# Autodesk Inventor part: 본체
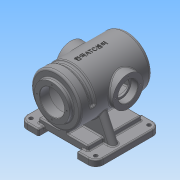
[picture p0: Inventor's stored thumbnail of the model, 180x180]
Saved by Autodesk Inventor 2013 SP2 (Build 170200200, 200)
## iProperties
Created: 2015-10
Part Number: 본체
Document SubType Name: Modeling
Designer: mdu
Density: 2.71 g/cm^3
Material: 알루미늄 6061
Mass: 4592.12 g
Surface Area: 2715.66 cm^2
Volume: 1694.51 cm^3
Author: mdu
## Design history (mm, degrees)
sketch "스케치1"
  geometry: L1 (-100, 85)-(-50, 85); L2 (-50, 85)-(-50, -85); L3 (-50, -85)-(-100, -85); L4 (-100, -85)-(-100, 85); L5 (50, 85)-(100, 85); L6 (100, 85)-(100, -85); L7 (100, -85)-(50, -85); L8 (50, -85)-(50, 85); 3 further points
  constraints: 16 end point, 4 parallel, 2 equal length, 2 horizontal, 2 horizontal alignment, 2 midpoint, 2 perpendicular
  dimensions: "d0" = 100 distance between parallel lines of L8 L2; "d1" = 170 distance of L3.end L1.start; "d3" = 200 distance between parallel lines of L6 L4; "d4" = 50 distance from line of point (0, 0) L2 (= 0.5 x d0)
extrude "돌출1" new body sketch "스케치1" distance "d5" = 16; taper "d6" = 0 deg
node "작업 평면1"
sketch "스케치2"
  geometry: L1 (-65, 70)-(65, 70); L2 (65, 70)-(65, -70); L3 (65, -70)-(-65, -70); L4 (-65, -70)-(-65, 70); 3 further points
  constraints: 8 end point, 2 midpoint, 2 parallel, 1 horizontal, 1 horizontal alignment, 1 perpendicular, 1 vertical alignment
  dimensions: "d8" = 130 distance of L2.end L3.end; "d9" = 140 distance of L1.end L2.end
extrude "돌출2" join sketch "스케치2" distance "d10" = 20; taper "d11" = 0 deg
sketch "스케치3"
  geometry: L1 (-100, 110)-(100, 110); L2 (85, 0)-(-85, 0) reference; L3 (100, 110)-(100, 175); L4 (100, 175)-(-90, 175); L5 (-90, 175)-(-90, 156); L6 (-90, 156)-(-100, 156); L7 (-100, 156)-(-100, 110); L8 (90, 110)-(90, 165); L9 (90, 165)-(-75, 165); L10 (-75, 165)-(-75, 110); L11 (-100, 142.5)-(-75, 142.5); 3 further points
  constraints: 20 end point, 5 perpendicular, 4 parallel, 4 point on line, 2 midpoint, 1 horizontal, 1 vertical alignment
  dimensions: "d12" = 110 distance from line of L2 L1.end; "d13" = 200 distance of L1.start L1.end; "d14" = 130 diameter of L4 L1; "d15" = 92 diameter of L6 L1; "d16" = 10 distance of L5.end L6.end; "d42" = 110 diameter of L9 L1; "d43" = 10 distance between parallel lines of L3 L8; "d44" = 25 distance between parallel lines of L10 L7; "d45" = 65 diameter of L11 L1
revolve "회전1" sketch "스케치3" stored, may be unused: angle "d17" = 90 deg
sketch "스케치4"
  geometry: L1 (-50, 70)-(50, 70) reference; L2 (50, -70)-(-50, -70) reference; L3 (-10, 70)-(-10, -70); L4 (10, -70)-(10, 70); 1 further point
  constraints: 4 end point, 4 point on line, 2 perpendicular
  dimensions: "d18" = 20 distance between parallel lines of L4 L3; "d19" = 10 distance from line of point (0, 0) L3
extrude "돌출3" join sketch "스케치4" stored distance "d20" = 10; taper "d21" = 0 deg
node "작업 평면2"
sketch "스케치5"
  geometry: L1 (-50, -8)-(0, -8) reference; L2 (100, -8)-(150, -8) reference; L3 (-40, -8)-(-8.943, -74.601); L4 (140, -8)-(108.943, -74.601); L5 (-50, 8)-(-50, -8) reference; L6 (150, 8)-(150, -8) reference; A1 r 65 centre (50, -102) between (-8.943, -74.601) and (108.943, -74.601) reference; 1 further point
  constraints: 4 end point, 2 point on circle, 2 point on line, 1 equal length
  dimensions: "d23" = 10 distance from line of L3.start L5; "d24" = 10 distance from line of L4.start L6; "d25" = 25 deg angle of L3 L5
feature "리브1" sketch "스케치5" dims "d26" = 1, "d27" = 20, "d28" = 0
node "작업 평면3"
sketch "스케치6"
  geometry: L1 (100, 156)-(100, 64) reference; C1 r 40 at (-25, 110); 2 further points
  constraints: 1 centre point, 1 horizontal alignment, 1 midpoint
  dimensions: "d37" = 80 diameter of C1; "d38" = 125 distance from line of C1.centre L1
extrude "돌출4" join sketch "스케치6" stored distance "d39" = 10; taper "d40" = 0 deg
hole "구멍1" diameter "d48" = 42; stored, may be unused: countersink angle "d52" = 90 deg, drill point angle "d54" = 118 deg; dims "d46" = 10, "d47" = 10, "d49" = 6, "d50" = 52, "d51" = 18, "d53" = 8
sketch "스케치7"
  geometry: C1 r 40 at (0, 0) reference; 2 further points
  constraints: 1 horizontal alignment
  dimensions: "d55" = 32.5 distance of point (32.5, 0) C1.centre
hole "구멍2" sketch "스케치7" at (32.5, 0) diameter "d56" = 3.242; stored, may be unused: countersink angle "d60" = 90 deg, drill point angle "d62" = 118 deg; dims "d57" = 11, "d58" = 52, "d59" = 18, "d61" = 13
sketch "스케치8"
  geometry: C1 r 46 at (0, 0) reference; 2 further points
  constraints: 1 vertical alignment
  dimensions: "d66" = 39 distance of C1.centre point (0, 39)
hole "구멍3" sketch "스케치8" at (0, 39) diameter "d67" = 3.242; stored, may be unused: countersink angle "d71" = 90 deg, drill point angle "d73" = 118 deg; dims "d68" = 11, "d69" = 52, "d70" = 18, "d72" = 13
fillet "모깎기7" dims "d77" = 20, "d78" = 5, "d79" = 3, "d80" = 10, "d107" = 10
fillet "모깎기8" dims "d81" = 3
fillet "모깎기9" dims "d82" = 3
fillet "모깎기10" dims "d83" = 3, "d84" = 0.3
chamfer "모따기1" distance "d85" = 1; stored, may be unused: second distance "d86" = 2, angle "d87" = 45 deg
node "작업 평면4"
sketch "스케치10"
  geometry: 5 further points
  constraints: 2 horizontal alignment, 2 vertical alignment
  dimensions: "d90" = 170 distance of point (85, 70) point (-85, 70); "d91" = 140 distance of point (-85, 70) point (-85, -70); "d92" = 70 vertical distance of point (0, 0) point (-85, -70) (= 0.5 x d91); "d93" = 85 horizontal distance of point (0, 0) point (-85, 70) (= 0.5 x d90)
hole "구멍4" sketch "스케치10" at (-85, 70), (85, 70), (85, -70), (-85, -70) diameter "d94" = 10; stored, may be unused: countersink angle "d98" = 90 deg, drill point angle "d100" = 118 deg; dims "d95" = 6, "d96" = 4, "d97" = 2, "d99" = 8
node "작업 평면5"
sketch "스케치12" dims "d22" = -90
  geometry: L1 (-65, -90)-(65, -90) reference; L2 (65, 85)-(-65, 85) reference; L3 (0, -90)-(0, 85); 3 further points
  constraints: 3 midpoint, 2 end point, 1 coincident, 1 other
feature "엠보싱3" sketch "스케치12" dims "d105" = 1, "d106" = 0
node "작업축1"
sketch "스케치13"
  geometry: L1 (-85, 175)-(90, 175) reference; L2 (-65, 175)-(-50, 175); L3 (-50, 175)-(-50, 170); L4 (-50, 170)-(-65, 170); L5 (-65, 170)-(-65, 175); L6 (-90, 50)-(-90, 170) reference; L7 (-140, 110)-(140, 110) reference; 1 further point
  constraints: 8 end point, 2 parallel, 1 horizontal, 1 perpendicular, 1 point on line
  dimensions: "d108" = 25 distance between parallel lines of L5 L6; "d109" = 15 distance of L3.end L4.end; "d110" = 5 distance of L2.end L3.end
revolve "회전2" sketch "스케치13" stored, may be unused: angle "d111" = 180 deg
fillet "모깎기11" dims "d112" = 5
fillet "모깎기12" dims "d113" = 5
fillet "모깎기13" dims "d114" = 3
node "솔리드1"
mirror "대칭1"
pattern_circular "원형 패턴1" dims angle "d64" = 360 deg
mirror "대칭3"
pattern_circular "원형 패턴2" dims angle "d75" = 360 deg
other parameters: "d7" = 8, "d36" = -75
